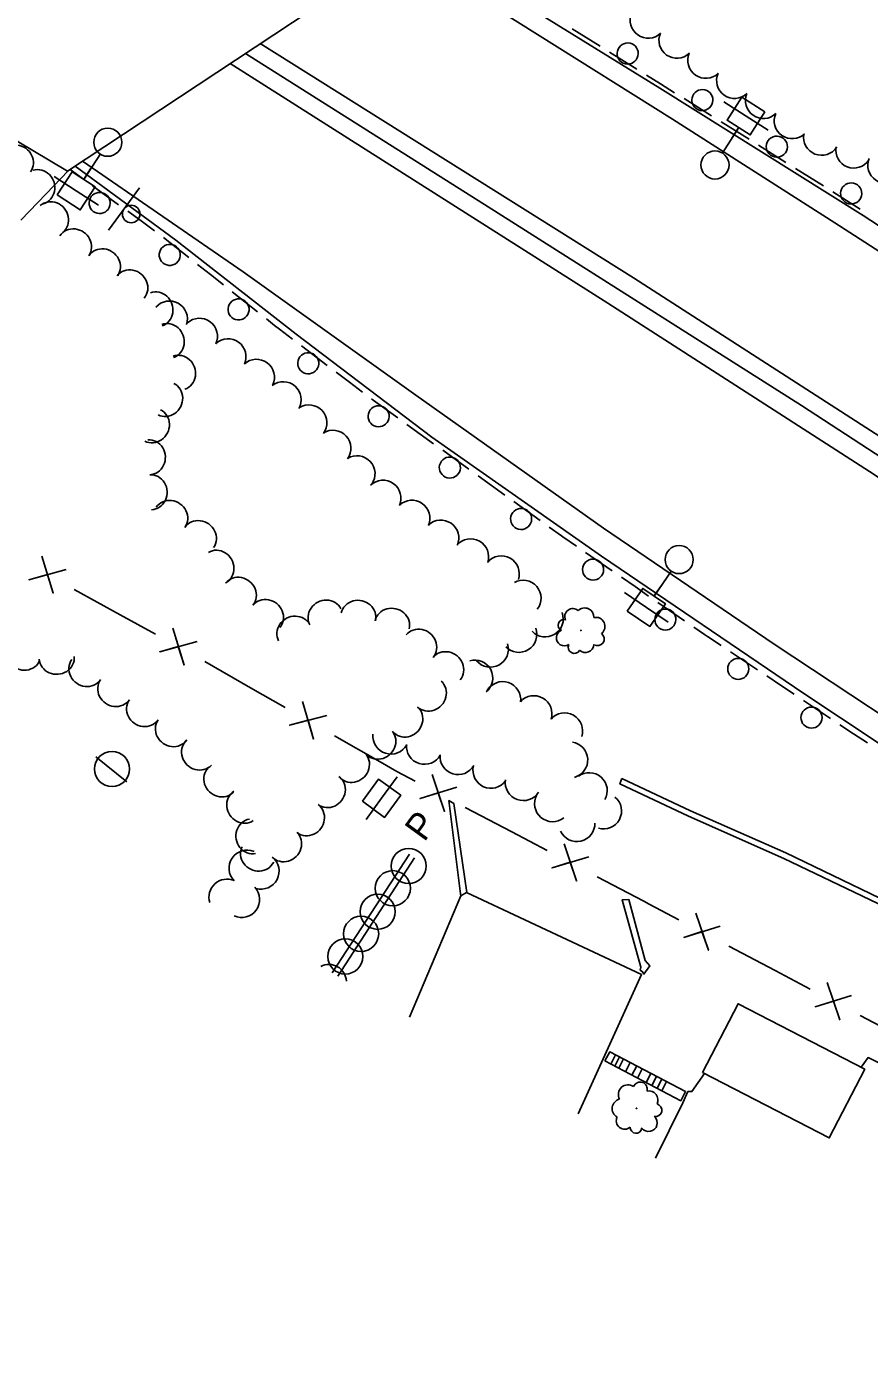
# Model space of a CAD drawing. Extents: x 1746010 to 1754829, y 655801 to 663091.
# Drawn here: x 1747433.7 to 1747673.4, y 661903.4 to 662282.7 of the extents above; entities that cross this region are included whole.
import ezdxf

# ---------------------------------------------------------------- set-up
doc = ezdxf.new("R2010")
doc.units = 0
for name, color, linetype in [('SURVEY - AERIAL SURVEY - Photo Control - Points - Elevations', 7, 'Continuous'), ('SURVEY - AERIAL SURVEY - Photo Control - Points - Locators', 7, 'Continuous'), ('SURVEY - AERIAL SURVEY - Photo Control - Points - Numbers', 7, 'Continuous'), ('SURVEY - AERIAL SURVEY - Photo Control with Text', 7, 'Continuous'), ('SURVEY - CENTERLINE - Existing Roads - Development', 7, 'Continuous'), ('SURVEY - CENTERLINE - Existing Roads Curve Text', 7, 'Continuous'), ('SURVEY - CENTERLINE - Existing Roads Text', 7, 'Continuous')]:
    doc.layers.add(name, color=color, linetype=linetype)

msp = doc.modelspace()

# ---------------------------------------------------------------- linework, layer by layer
at = {"layer": 'SURVEY - AERIAL SURVEY - Photo Control - Points - Elevations'}
for points in [[(1747292.12, 662332.97), (1747297.32, 662336.24), (1747395.66, 662401.33), (1747546.51, 662308.57), (1747445.3, 662241.61)], [(1747445.3, 662241.61), (1747292.12, 662332.97)], [(1747985.76, 661838.11), (1747954.49, 661859.84), (1747913.88, 661887.28), (1747866.65, 661919.88), (1747823.19, 661949.53), (1747794.28, 661968.76), (1747775.03, 661980.63), (1747741.82, 661998.46), (1747710.25, 662014.92), (1747675.84, 662033.13), (1747649.1, 662045.94), (1747622.01, 662057.94), (1747602.48, 662067.13), (1747603.06, 662068.67)], [(1747686.7, 662029.24), (1747676.47, 662034.65), (1747649.67, 662047.49), (1747622.57, 662059.5), (1747603.06, 662068.67)], [(1747557.18, 662035.12), (1747553.81, 662062.41), (1747555.17, 662061.58), (1747558.93, 662036.21)], [(1747608.42, 662014.95), (1747603.1, 662034.12), (1747605, 662034.24), (1747609.69, 662016.93), (1747610.94, 662015.38), (1747609.29, 662013), (1747608.9, 662013.68), (1747608.27, 662014.12)], [(1747608.27, 662014.12), (1747608.42, 662014.95)]]:
    msp.add_lwpolyline(points, dxfattribs=at)
at = {"layer": 'SURVEY - AERIAL SURVEY - Photo Control - Points - Locators'}
for points in [[(1748066.62, 661959.87), (1747978.51, 662021.63), (1747901.08, 662075.95), (1747819.42, 662131.94), (1747745.85, 662180.6), (1747671.72, 662228.98), (1747613.87, 662265.2), (1747545.13, 662307.66)], [(1748067.96, 661950.85), (1747977.15, 662016.22), (1747914.56, 662059.52), (1747827.89, 662119.16), (1747755.21, 662167.87), (1747663.67, 662226.9), (1747617.46, 662256.37), (1747540.61, 662304.67)], [(1747500.14, 662277.89), (1747606.38, 662211.23), (1747699.06, 662151.4), (1747807.18, 662080.79), (1747921.23, 662001.72), (1748045.01, 661913.44)], [(1748036.84, 661905.72), (1747955.58, 661964.08), (1747865.84, 662027.24), (1747772.62, 662090.53), (1747673.46, 662156.1), (1747599.02, 662204.01), (1747520.15, 662254.13), (1747491.6, 662272.24)], [(1747449.54, 662244.42), (1747495.25, 662212.96), (1747544.44, 662177.78), (1747597.81, 662139.99), (1747646.37, 662106.97), (1747700.87, 662070.9), (1747757.2, 662033.9), (1747810.92, 661997.83), (1747873.88, 661953.8), (1747937.26, 661909.07), (1748007.34, 661858.36)], [(1747447.41, 662243.01), (1747476.14, 662221.97), (1747510.35, 662195.13), (1747548.92, 662165.86), (1747597.25, 662131.99), (1747654.78, 662092.84), (1747686.43, 662071.96), (1747763.1, 662019.85), (1747803.08, 661990.33), (1747877.22, 661937.39), (1747950.5, 661884.69), (1747998.74, 661850.34)], [(1747558.8, 662036.27), (1747557.23, 662035.26)], [(1747590.56, 661973.19), (1747608.58, 662012.88), (1747558.8, 662036.27)], [(1747557.23, 662035.26), (1747542.55, 662000.73)], [(1747671.1, 661986.48), (1747673.09, 661989.24), (1747705.69, 661972.83), (1747706.92, 661972.21), (1747705.44, 661969.51)], [(1747620.35, 661976.33), (1747621.83, 661979.58), (1747622.97, 661979.55), (1747626.54, 661984.73)], [(1747620.35, 661976.33), (1747612.56, 661960.57)]]:
    msp.add_lwpolyline(points, dxfattribs=at)
at = {"layer": 'SURVEY - AERIAL SURVEY - Photo Control - Points - Numbers'}
for points in [[(1747592.82, 662279.62), (1747588.84, 662282.1)], [(1747596.81, 662277.13), (1747592.82, 662279.62)], [(1747495.88, 662275.08), (1747565, 662231.38), (1747654.17, 662174.84), (1747729.86, 662125.51), (1747795.86, 662081.53), (1747865.54, 662033.9), (1747933.39, 661986.48), (1748007.95, 661933.43), (1748040.01, 661910.33)], [(1747607.33, 662270.58), (1747599.53, 662275.44)], [(1747614.03, 662266.4), (1747610.04, 662268.89)], [(1747618.02, 662263.91), (1747614.03, 662266.4)], [(1747628.54, 662257.35), (1747620.74, 662262.22)], [(1747635.25, 662253.17), (1747631.26, 662255.66)], [(1747639.23, 662250.69), (1747639.22, 662250.7), (1747635.25, 662253.17)], [(1747649.73, 662244.08), (1747641.94, 662248.98)], [(1747445.99, 662242.07), (1747449.8, 662239.31)], [(1747656.41, 662239.87), (1747652.43, 662242.37)], [(1747452.39, 662237.43), (1747459.83, 662232.03)], [(1747660.38, 662237.36), (1747656.41, 662239.87)], [(1747670.88, 662230.75), (1747663.09, 662235.66)], [(1747462.42, 662230.15), (1747466.22, 662227.39)], [(1747466.22, 662227.39), (1747470.02, 662224.63)], [(1747472.59, 662222.72), (1747479.79, 662217.01)], [(1747482.3, 662215.03), (1747485.98, 662212.11)], [(1747485.98, 662212.11), (1747489.66, 662209.19)], [(1747492.16, 662207.21), (1747499.36, 662201.5)], [(1747501.86, 662199.51), (1747504.21, 662197.65), (1747505.57, 662196.62)], [(1747505.57, 662196.62), (1747509.31, 662193.78)], [(1747511.86, 662191.84), (1747519.19, 662186.29)], [(1747521.74, 662184.35), (1747525.48, 662181.51)], [(1747525.48, 662181.51), (1747529.22, 662178.67)], [(1747531.77, 662176.74), (1747532.26, 662176.37), (1747539.23, 662171.35)], [(1747541.82, 662169.48), (1747545.63, 662166.73)], [(1747545.63, 662166.73), (1747549.45, 662163.98)], [(1747552.04, 662162.11), (1747559.51, 662156.74)], [(1747562.1, 662154.87), (1747565.91, 662152.12)], [(1747565.91, 662152.12), (1747569.73, 662149.37)], [(1747572.32, 662147.5), (1747579.79, 662142.12)], [(1747582.38, 662140.26), (1747585.83, 662137.77), (1747586.2, 662137.52)], [(1747586.2, 662137.52), (1747590.07, 662134.84)], [(1747592.7, 662133.03), (1747600.27, 662127.8)], [(1747602.9, 662125.98), (1747606.77, 662123.31)], [(1747606.77, 662123.31), (1747610.63, 662120.64)], [(1747613.27, 662118.82), (1747620.84, 662113.59)], [(1747623.47, 662111.77), (1747626.51, 662109.67), (1747627.35, 662109.11)], [(1747627.35, 662109.11), (1747631.26, 662106.51)], [(1747633.92, 662104.74), (1747641.58, 662099.64)], [(1747644.25, 662097.87), (1747648.16, 662095.26)], [(1747648.16, 662095.26), (1747652.07, 662092.66)], [(1747654.74, 662090.88), (1747662.39, 662085.79)], [(1747665.06, 662084.01), (1747668.97, 662081.41)], [(1747668.97, 662081.41), (1747672.88, 662078.8)]]:
    msp.add_lwpolyline(points, dxfattribs=at)
for centre, start, end in [((1747604.68, 662275.06), 347.236, 347.2221), ((1747625.93, 662261.81), 347.1142, 347.1003), ((1747647.12, 662248.55), 346.8702, 346.8562), ((1747668.28, 662235.23), 346.8702, 346.8562), ((1747454.41, 662232.51), 165.801, 165.7871), ((1747474.38, 662217.74), 163.3128, 163.2988), ((1747493.94, 662202.22), 163.3128, 163.2988), ((1747513.78, 662186.88), 164.6029, 164.5889), ((1747533.8, 662171.81), 166.0125, 165.9985), ((1747554.08, 662157.2), 166.0125, 165.9985), ((1747574.36, 662142.58), 166.0125, 165.9985), ((1747594.84, 662128.15), 167.1645, 167.1505), ((1747615.41, 662113.94), 167.1645, 167.1505), ((1747636.16, 662099.89), 168.186, 168.172), ((1747656.98, 662086.03), 168.186, 168.172)]:
    msp.add_arc(centre, 3, start, end, dxfattribs=at)
at = {"layer": 'SURVEY - AERIAL SURVEY - Photo Control with Text'}
for p, q in [((1747456.97, 662224.73), (1747465.79, 662236.86)), ((1747453.3, 662074.9), (1747462.17, 662067.7)), ((1747457.93, 662071.41), (1747457.93, 662071.41)), ((1747542.55, 662047.17), (1747520.56, 662013.34)), ((1747522.18, 662012.42), (1747544.03, 662046.07)), ((1747542.37, 662043.73), (1747542.37, 662043.73)), ((1747537.85, 662037.42), (1747537.85, 662037.42)), ((1747533.54, 662030.71), (1747533.54, 662030.71)), ((1747528.83, 662024.44), (1747528.83, 662024.44)), ((1747524.34, 662017.99), (1747524.34, 662017.99))]:
    msp.add_line(p, q, dxfattribs=at)
for centre, radius in [((1747463.39, 662229.39), 2.5), ((1747457.96, 662071.42), 5), ((1747542.37, 662043.77), 5), ((1747537.84, 662037.46), 5), ((1747533.53, 662030.75), 5), ((1747528.82, 662024.48), 5), ((1747524.33, 662018.03), 5)]:
    msp.add_circle(centre, radius, dxfattribs=at)
msp.add_arc((1747519.63, 662010.77), 5, 2.8359, 117.478, dxfattribs=at)
at = {"layer": 'SURVEY - CENTERLINE - Existing Roads - Development'}
for p, q in [((1747599.93, 661987.39), (1747601.26, 661990.01)), ((1747601.06, 661986.79), (1747602.4, 661989.42)), ((1747602.13, 661986.23), (1747603.47, 661988.85)), ((1747604.02, 661985.24), (1747605.35, 661987.86)), ((1747605.9, 661984.25), (1747607.24, 661986.88)), ((1747607.47, 661983.43), (1747608.8, 661986.05)), ((1747609.95, 661982.13), (1747611.28, 661984.75)), ((1747611.58, 661981.28), (1747612.91, 661983.9)), ((1747613.06, 661980.5), (1747614.4, 661983.12)), ((1747614.37, 661979.81), (1747615.71, 661982.43))]:
    msp.add_line(p, q, dxfattribs=at)
for points in [[(1747439.16, 662235.13), (1747445.42, 662241.69)], [(1747432.01, 662227.63), (1747439.16, 662235.13)], [(1747444.93, 662128.2), (1747434.3, 662125.27), (1747439.57, 662126.76), (1747441.22, 662121.46), (1747438.01, 662132.01)], [(1747460.29, 662115.24), (1747447.15, 662122.48)], [(1747470.27, 662109.74), (1747460.29, 662115.24)], [(1747482.16, 662107.69), (1747471.53, 662104.77), (1747476.8, 662106.26), (1747478.45, 662100.96), (1747475.24, 662111.51)], [(1747497.37, 662094.52), (1747484.36, 662101.95)], [(1747507.25, 662088.86), (1747497.37, 662094.52)], [(1747519.04, 662086.66), (1747508.47, 662083.84), (1747513.71, 662085.28), (1747515.32, 662079.93), (1747512.19, 662090.58)], [(1747534.21, 662073.44), (1747521.21, 662080.88)], [(1747544.19, 662067.97), (1747538.98, 662070.71), (1747534.21, 662073.44)], [(1747556.05, 662066.19), (1747545.59, 662062.99), (1747550.78, 662064.61), (1747552.57, 662059.32), (1747549.07, 662069.86)], [(1747571.68, 662053.51), (1747558.42, 662060.48)], [(1747581.75, 662048.21), (1747571.68, 662053.51)], [(1747593.6, 662046.43), (1747583.15, 662043.23), (1747588.33, 662044.85), (1747590.13, 662039.56), (1747586.62, 662050.1)], [(1747609.23, 662033.75), (1747595.98, 662040.72)], [(1747619.27, 662028.45), (1747610.84, 662032.9), (1747609.23, 662033.75)], [(1747631.04, 662026.7), (1747620.69, 662023.46), (1747625.82, 662025.1), (1747627.64, 662019.79), (1747624.09, 662030.36)], [(1747646.62, 662014), (1747633.43, 662020.97)], [(1747656.65, 662008.71), (1747646.62, 662014)], [(1747668.42, 662006.95), (1747658.08, 662003.71), (1747663.21, 662005.35), (1747665.03, 662000.04), (1747661.47, 662010.62)], [(1747684.01, 661994.26), (1747670.81, 662001.23)]]:
    msp.add_lwpolyline(points, dxfattribs=at)
for points in [[(1747626.01, 661985.01), (1747662.04, 661966.39), (1747672.14, 661985.94), (1747636.11, 662004.56)], [(1747598.22, 661988.28), (1747619.78, 661976.97), (1747621.16, 661979.57), (1747599.6, 661990.88)]]:
    msp.add_lwpolyline(points, close=True, dxfattribs=at)
at = {"layer": 'SURVEY - CENTERLINE - Existing Roads Curve Text'}
for p, q in [((1747638.36, 662257.27), (1747632.03, 662261.29)), ((1747638.36, 662257.27), (1747644.7, 662253.25)), ((1747631.61, 662246.64), (1747636.27, 662253.98)), ((1747636.06, 662253.64), (1747634.34, 662250.94)), ((1747454.62, 662246.53), (1747449.89, 662239.23)), ((1747450.1, 662239.57), (1747451.84, 662242.25)), ((1747447.77, 662235.96), (1747441.47, 662240.03)), ((1747447.77, 662235.96), (1747454.06, 662231.88)), ((1747617.12, 662127.78), (1747612.21, 662120.6)), ((1747612.43, 662120.93), (1747614.24, 662123.57)), ((1747610, 662117.39), (1747603.82, 662121.62)), ((1747610, 662117.39), (1747616.19, 662113.15)), ((1747534.64, 662063.08), (1747539.05, 662069.14)), ((1747534.64, 662063.08), (1747530.22, 662057.02))]:
    msp.add_line(p, q, dxfattribs=at)
for points in [[(1747643.75, 662258.47), (1747639.56, 662251.89), (1747632.98, 662256.07), (1747637.16, 662262.66)], [(1747442.37, 662234.8), (1747446.61, 662241.35), (1747453.16, 662237.11), (1747448.92, 662230.56)], [(1747604.58, 662116.37), (1747608.99, 662122.81), (1747615.43, 662118.4), (1747611.02, 662111.96)], [(1747529.19, 662062.22), (1747533.78, 662068.53), (1747540.08, 662063.94), (1747535.5, 662057.63)]]:
    msp.add_lwpolyline(points, close=True, dxfattribs=at)
for centre in [(1747456.74, 662249.8), (1747629.52, 662243.34), (1747619.33, 662131)]:
    msp.add_circle(centre, 4, dxfattribs=at)
at = {"layer": 'SURVEY - CENTERLINE - Existing Roads Text'}
for centre, radius in [((1747591.36, 662110.83), 0.0798), ((1747607.18, 661974.77), 0.0843)]:
    msp.add_circle(centre, radius, dxfattribs=at)
for centre, radius, start, end in [((1747610.5, 662284.54), 5.13, 156.6967, 313.4901), ((1747618.7, 662278.84), 5.13, 156.6967, 313.4901), ((1747626.9, 662273.13), 5.13, 156.6967, 313.4901), ((1747635.11, 662267.4), 5.13, 156.5713, 313.3647), ((1747643.31, 662261.68), 5.13, 156.5713, 313.3647), ((1747651.51, 662255.95), 5.13, 156.5713, 313.3647), ((1747659.88, 662251.22), 5.13, 169.9271, 326.7205), ((1747669.03, 662247.57), 5.13, 169.9271, 326.7205), ((1747678.15, 662243.24), 5.13, 157.7008, 314.4942), ((1747474.28, 662199.48), 5.13, 342.3192, 139.1126), ((1747482.84, 662194.58), 5.13, 335.4683, 132.2618), ((1747490.95, 662188.74), 5.13, 335.4683, 132.2618), ((1747499.06, 662182.89), 5.13, 335.4683, 132.2618), ((1747506.65, 662176.52), 5.13, 330.519, 127.3124), ((1747513.97, 662169.91), 5.13, 324.6689, 121.4623), ((1747520.81, 662162.68), 5.13, 324.6689, 121.4623), ((1747527.66, 662155.44), 5.13, 324.6689, 121.4623), ((1747535.05, 662148.46), 5.13, 336.6508, 133.4442), ((1747543.28, 662142.78), 5.13, 336.6508, 133.4442), ((1747551.49, 662137.12), 5.13, 336.8248, 133.6182), ((1747559.97, 662131.79), 5.13, 342.1723, 138.9657), ((1747568.71, 662126.93), 5.13, 342.1723, 138.9657), ((1747574.91, 662120), 5.13, 322.1502, 118.9436), ((1747581.22, 662114.12), 5.13, 223.4778, 20.2712), ((1747589.06, 662114.77), 2.29, 48.0884, 204.8773), ((1747592.42, 662114.63), 2.61, 357.1411, 134.6654), ((1747573.71, 662109.73), 5.13, 223.4778, 20.2712), ((1747586.45, 662112.34), 1.57, 70.2045, 248.9502), ((1747595.64, 662111.98), 2.59, 308.037, 103.8754), ((1747586.68, 662108.73), 2.28, 110.2252, 303.6449), ((1747596.09, 662108.41), 1.91, 238.2899, 53.2901), ((1747565.61, 662105.51), 5.13, 219.9231, 16.7166), ((1747589.49, 662106.04), 1.74, 152.8439, 330.163), ((1747592.64, 662107.01), 2.46, 228.1309, 354.9766), ((1747561.17, 662097.29), 5.13, 309.3803, 106.1738), ((1747569.11, 662091.14), 5.13, 352.7628, 149.5562), ((1747578, 662087.14), 5.13, 341.9098, 138.7032), ((1747586.72, 662082.24), 5.13, 341.9098, 138.7032), ((1747537.31, 662080.77), 5.13, 174.2333, 331.0267), ((1747546.86, 662077.85), 5.13, 174.2333, 331.0267), ((1747588.19, 662073.98), 5.13, 284.842, 81.6355), ((1747556.42, 662074.92), 5.13, 174.2333, 331.0267), ((1747565.76, 662071.03), 5.13, 167.4213, 324.2147), ((1747593.74, 662065.22), 5.13, 330.2488, 127.0422), ((1747574.98, 662067.53), 5.13, 171.3012, 328.0946), ((1747583.31, 662061.53), 5.13, 151.5665, 308.3599), ((1747597.8, 662059.44), 5.13, 253.7173, 50.5107), ((1747590.22, 662055.87), 5.13, 204.8571, 1.6506), ((1747496.35, 662043.15), 5.13, 67.1278, 223.9212), ((1747500.36, 662042.33), 5.13, 253.9791, 50.7726), ((1747490.66, 662034.91), 5.13, 66.4408, 197.6836), ((1747494.82, 662034.26), 5.13, 245.4983, 42.2918), ((1747604.76, 661978.77), 2.73, 54.0932, 209.9317), ((1747608.25, 661980.27), 2.02, 344.3461, 159.3464), ((1747610.69, 661977.18), 2.6, 334.1872, 101.0329), ((1747603.02, 661974.73), 2.75, 103.1974, 240.7216), ((1747612.59, 661974.27), 1.83, 258.9002, 76.2193), ((1747603.85, 661971.28), 2.41, 154.1447, 310.9336), ((1747610.68, 661970.63), 2.41, 216.2815, 49.7012), ((1747607.08, 661969.35), 1.66, 176.2608, 355.0065)]:
    msp.add_arc(centre, radius, start, end, dxfattribs=at)
for centre, major_axis in [((1747430.68, 662244.23), (4.1, -2.86)), ((1747436.93, 662237.05), (1.44, -4.79)), ((1747440.75, 662227.98), (3.22, -3.83)), ((1747447.19, 662220.34), (4.12, -2.84)), ((1747455.43, 662214.66), (4.12, -2.84)), ((1747463.25, 662208.64), (3.86, -3.18)), ((1747470.55, 662202.23), (1.68, -4.71)), ((1747473.77, 662193.21), (1.68, -4.71)), ((1747476.98, 662184.19), (1.68, -4.71)), ((1747473.29, 662176.67), (-2.25, -4.47)), ((1747469.51, 662169.17), (-2.25, -4.47)), ((1747468.42, 662160.13), (0.26, -4.99)), ((1747468.94, 662150.18), (0.26, -4.99)), ((1747474.58, 662143.04), (4.09, -2.87)), ((1747482.76, 662137.3), (4.09, -2.87)), ((1747487.87, 662128.74), (2.5, -4.33)), ((1747494.13, 662121.15), (3.87, -3.16)), ((1747501.87, 662114.83), (3.87, -3.16)), ((1747518.65, 662114.72), (4.44, 2.29)), ((1747528.03, 662114.69), (4.87, -1.14)), ((1747509.79, 662110.14), (4.44, 2.29)), ((1747537.65, 662112.43), (4.87, -1.14)), ((1747545.48, 662106.38), (3.84, -3.2)), ((1747432.77, 662104.25), (-4.65, 1.83)), ((1747553.14, 662099.98), (3.84, -3.2)), ((1747442.22, 662103.05), (-4.98, -0.4)), ((1747450.57, 662099.67), (-4.1, 2.86)), ((1747458.77, 662093.97), (-4.1, 2.86)), ((1747548.25, 662092.73), (-3.36, -3.7)), ((1747466.97, 662088.26), (-4.1, 2.86)), ((1747541.54, 662085.35), (-3.36, -3.7)), ((1747475.17, 662082.54), (-4.1, 2.86)), ((1747533.83, 662079), (-3.88, -3.15)), ((1747482.6, 662075.93), (-3.62, 3.45)), ((1747526.36, 662072.43), (-3.45, -3.62)), ((1747488.92, 662068.28), (-3.59, 3.48)), ((1747519.54, 662065.28), (-2.98, -4.01)), ((1747495.38, 662060.87), (-2.76, 4.17)), ((1747513.6, 662057.28), (-2.98, -4.01)), ((1747497.91, 662052.22), (-0.89, 4.92)), ((1747507.05, 662049.84), (-3.53, -3.54)), ((1747499.44, 662047.08), (-4.51, 2.16))]:
    msp.add_ellipse(centre, major_axis=major_axis, ratio=0.940188, start_param=0, end_param=3.141593, dxfattribs=at)

# ---------------------------------------------------------------- texts
at = {"layer": 'SURVEY - CENTERLINE - Existing Roads Curve Text'}
msp.add_text('P', height=7.48, rotation=53.9474, dxfattribs=at).set_placement((1747546.8, 662050.39))

doc.saveas('drawing.dxf')
